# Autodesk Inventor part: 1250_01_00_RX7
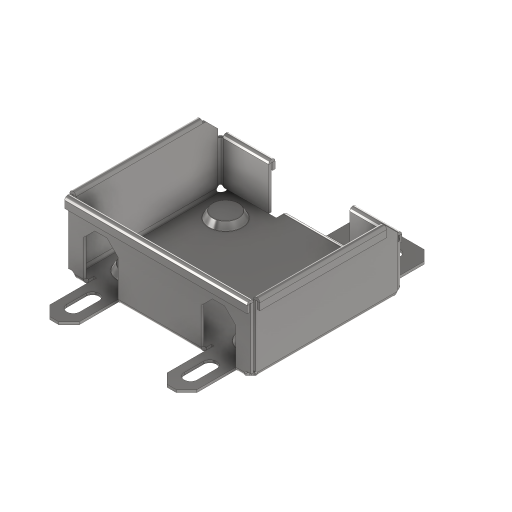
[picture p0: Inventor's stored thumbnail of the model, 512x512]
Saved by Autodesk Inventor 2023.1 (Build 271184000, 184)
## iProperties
Company: Fabian Stasiak CAD Consulting
Category: Autodesk® Inventor® Tutorial Series
RuleStatus: InUse
Created: 2005-11
Part Number: 1250_01_00_RX7
Material: Steel
Document SubType Name: Sheet Metal
Designer: F.Stasiak
Density: 7.85 g/cm^3
Sheet Metal Rule: Steel 2.5 mm/Round
Flat Pattern Width: 32.8562 cm
Flat Pattern Length: 33.224 cm
Flat Pattern Area: 1091.62 cm^2
Sheet Metal Width: 328,562 mm
Sheet Metal Length: 332,240 mm
Sheet Metal Area: 109161,518 mm^2
Appearance: Semi-Polished
Description: Mounting Box RX7
Catalog Web Link: www.expertbooks.eu
FLATAREA: =<FLAT PATTERN AREA>
Thickness: 2,5
Author: F.Stasiak
Subject: Sheet Metal Design. Basic and Advanced techniques
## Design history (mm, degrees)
node "Powierzchnia1"
  sketch "Szkic2"
    geometry: L1 (-75, 90)-(75, 90); L2 (75, 90)-(75, -90); L3 (75, -90)-(-75, -90); L4 (-75, -90)-(-75, 90); L5 (0, 90)-(0, -90); 2 further points
    constraints: 10 end point, 3 midpoint, 2 parallel, 1 coincident, 1 horizontal, 1 perpendicular
    dimensions: "d2" = 150 distance of L2.end L3.end; "d3" = 180 distance of L1.end L2.end
node "Kołnierz6"
feature "Fazowanie narożnika3" dims "d68" = 20, "d69" = 6, angle "d70" = 45 deg
node "Kołnierz7"
feature "Narożnik4" dims "d156" = 10 (= CornerReliefSize), "d157" = 2.5 (= BendRadius), "d158" = 2.5 (= GapSize), "d159" = 0, "d160" = 10, "d244" = 2.5 (derived)
feature "Narożnik5" dims "d161" = 10 (= CornerReliefSize), "d162" = 2.5 (= BendRadius), "d163" = 2.5 (= GapSize), "d164" = 0, "d165" = 10, "d244" = 2.5 (derived)
node "Płaszczyzna konstrukcyjna2"
node "Powierzchnia3"
  sketch "Szkic11"
    geometry: L1 (-231, 119.076)-(-195, 119.076); L2 (-195, 119.076)-(-195, 49.076); L3 (-195, 49.076)-(-231, 49.076); L4 (-231, 49.076)-(-231, 119.076); L5 (-142.5, 44.076)-(-145, 44.076) reference; L6 (-142.5, 124.076)-(-145, 124.076) reference; L7 (-145, 167.518)-(-145, 0.634) reference; 3 further points
    constraints: 8 end point, 2 parallel, 1 horizontal, 1 perpendicular
    dimensions: "d82" = 5 distance between parallel lines of L5 L3; "d83" = 5 distance between parallel lines of L6 L1 (= d82); "d84" = 36 distance of L1.start L1.end; "d85" = 50 distance between parallel lines of L7 L2
feature "Fazowanie narożnika4" dims "d91" = 10, "d92" = 6, angle "d93" = 45 deg
feature "Gięcie10" dims "d94" = 2.5 (= BendReliefWidth), "d95" = 1.25 (= BendReliefDepth), "d96" = 5 (= MinimumRemnant), "d97" = 2.5 (= BendRadius), "d98" = 2.5 (= BendRadius), "d244" = 2.5 (derived), "SeamGap" = 0.01
sketch "Szkic19"
  geometry: L1 (-145, 167.518)-(-145, 119.076) reference; L2 (-145, 49.076)-(-145, 0.634) reference; L3 (-151.893, 49.076)-(-145, 49.076) reference; L4 (-151.893, 119.076)-(-151.893, 49.076) reference; L5 (-145, 119.076)-(-151.893, 119.076) reference; L6 (-145, 167.518)-(-145, 119.076) reference; L7 (7.645, 174.076)-(71.087, 174.076) reference; L8 (71.087, 174.076)-(71.087, -5.924) reference; L9 (71.087, -5.924)-(7.645, -5.924) reference; L10 (6.087, 168.153)-(6.087, 0) reference; L11 (-0.924, 169.076)-(-139.076, 169.076) reference; L12 (0, 0)-(0, 168.153) reference; L13 (-139.076, -0.924)-(-0.924, -0.924) reference; L14 (3.043, 1.033)-(3.043, 167.12) reference; L15 (53, 159.076)-(-5, 159.076); L16 (-5, 159.076)-(-5, 125.076); L17 (-5, 125.076)-(53, 125.076); L18 (53, 125.076)-(53, 159.076); L19 (-139.076, 174.076)-(-0.924, 174.076) reference; A1 r 5 centre (-143.043, 172.12) between (-145, 167.518) and (-139.076, 169.076) reference; A2 r 5 centre (3.043, 172.12) between (-0.924, 169.076) and (7.645, 174.076) reference; A3 r 5 centre (3.043, -3.967) between (7.645, -5.924) and (-0.924, -0.924) reference; A4 r 5 centre (-143.043, -3.967) between (-139.076, -0.924) and (-145, 0.634) reference; 1 further point
  constraints: 8 end point, 2 parallel, 1 horizontal, 1 perpendicular
  dimensions: "d166" = 34 distance of L15.end L16.end; "d167" = 15 distance between parallel lines of L15 L19; "d168" = 58 distance of L16.end L17.end; "d169" = 140 distance between parallel lines of L1 L16
feature "Wytnij2" sketch "Szkic19" dims "d170" = 2.5 (= Thickness), "d171" = 0
node "Kołnierz9"
feature "Fazowanie narożnika7" dims "d182" = 10, "d183" = 6, angle "d184" = 45 deg
feature "Fazowanie narożnika8" dims "d185" = 11, "d186" = 6, angle "d187" = 45 deg
mirror "Lustro2"
feature "Zawinięcie obrzeża6" dims "d188" = 2.5 (= BendReliefWidth), "d189" = 1.25 (= BendReliefDepth), "d190" = 5 (= MinimumRemnant), "d191" = 2.5 (= BendRadius), "d192" = 10 (= 4 x Thickness), "d193" = 1.25 (= 0.5 x Thickness), "d194" = 0.625 (= 0.5 x d193), "d244" = 2.5 (derived), "SeamGap" = 0.01
feature "Zawinięcie obrzeża7" dims "d195" = 2.5 (= BendReliefWidth), "d196" = 1.25 (= BendReliefDepth), "d197" = 5 (= MinimumRemnant), "d198" = 2.5 (= BendRadius), "d199" = 10 (= 4 x Thickness), "d200" = 1.25 (= 0.5 x Thickness), "d201" = 0.625 (= 0.5 x d200), "d244" = 2.5 (derived), "SeamGap" = 0.01
feature "Zawinięcie obrzeża8" dims "d202" = 2.5 (= BendReliefWidth), "d203" = 1.25 (= BendReliefDepth), "d204" = 5 (= MinimumRemnant), "d205" = 2.5 (= BendRadius), "d206" = 10 (= 4 x Thickness), "d207" = 1.25 (= 0.5 x Thickness), "d208" = 0.625 (= 0.5 x d207), "d244" = 2.5 (derived), "SeamGap" = 0.01
feature "Zawinięcie obrzeża9" dims "d209" = 2.5 (= BendReliefWidth), "d210" = 1.25 (= BendReliefDepth), "d211" = 5 (= MinimumRemnant), "d212" = 2.5 (= BendRadius), "d213" = 10 (= 4 x Thickness), "d214" = 1.25 (= 0.5 x Thickness), "d215" = 0.625 (= 0.5 x d214), "d244" = 2.5 (derived), "SeamGap" = 0.01
feature "Zawinięcie obrzeża10" dims "d216" = 2.5 (= BendReliefWidth), "d217" = 1.25 (= BendReliefDepth), "d218" = 5 (= MinimumRemnant), "d219" = 2.5 (= BendRadius), "d220" = 10 (= 4 x Thickness), "d221" = 1.25 (= 0.5 x Thickness), "d222" = 0.625 (= 0.5 x d221), "d244" = 2.5 (derived), "SeamGap" = 0.01
sketch "Szkic26"
  geometry: L1 (190.076, 31.5)-(190.076, 22.5) reference; L2 (134.076, 157.5)-(134.076, 128.5); L3 (133.736, 41.5)-(134.076, 12.5); L4 (190.076, 27)-(133.906, 27); L5 (189.537, 143)-(134.076, 143); 3 further points
  constraints: 8 end point, 5 midpoint, 1 parallel
sketch "Szkic27"
  geometry: L1 (-195, 119.076)-(-195, 49.076) reference; L2 (-231, 59.076)-(-231, 109.076) reference; L3 (-195, 84.076)-(-231, 84.076); 2 further points
  constraints: 3 midpoint, 2 end point
sketch "Szkic28"
  geometry: L1 (0, 0)-(138.153, 0) reference; L2 (144.076, 50)-(144.076, 1.558) reference; L3 (138.153, 170)-(0, 170) reference; L4 (-0.924, 126)-(-0.924, 44) reference; L5 (29.076, 25)-(119.076, 25); L6 (119.076, 25)-(119.076, 145); L7 (119.076, 145)-(29.076, 145); L8 (29.076, 145)-(29.076, 25); 1 further point
  constraints: 8 end point, 2 parallel, 1 horizontal, 1 perpendicular
  dimensions: "d229" = 25 distance between parallel lines of L5 L1; "d230" = 25 distance between parallel lines of L3 L7 (= d229); "d231" = 25 distance between parallel lines of L2 L6; "d232" = 30 distance between parallel lines of L4 L8
feature "iFeature18:1"
feature "iFeature18:2"
feature "iFeature5:1"
node "Definicja strony A"
feature "ع耀ظ耀ص耀ش耀س耀خ耀ح耀ا耀" dims "d0" = 180 deg, "d2" = 150, "d3" = 180, "d4" = 2.5 (= BendRadius), "d56" = 2.5 (= BendReliefWidth), "d57" = 1.25 (= BendReliefDepth), "d58" = 5 (= MinimumRemnant), "d59" = 2.5 (= BendRadius), "d60" = 70 (= WW), "d61" = 90 deg, "d62" = 2.5 (= BendRadius), "d63" = 10 (= CornerReliefSize), "d64" = 2.5 (= GapSize), "d65" = 2.5 (= JacobiRadiusSize), "d66" = 10, "d67" = 10, "d68" = 20, "d69" = 6, "d70" = 45 deg, "d71" = 2.5 (= BendReliefWidth), "d72" = 1.25 (= BendReliefDepth), "d73" = 5 (= MinimumRemnant), "d74" = 2.5 (= BendRadius), "d75" = 50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
feature "ٱ耀ٰ耀٭耀٬耀٫耀٦耀٥耀ٟ耀" dims "d0" = 180 deg, "d2" = 150, "d3" = 180, "d4" = 2.5 (= BendRadius), "d56" = 2.5 (= BendReliefWidth), "d57" = 1.25 (= BendReliefDepth), "d58" = 5 (= MinimumRemnant), "d59" = 2.5 (= BendRadius), "d60" = 70 (= WW), "d61" = 90 deg, "d62" = 2.5 (= BendRadius), "d63" = 10 (= CornerReliefSize), "d64" = 2.5 (= GapSize), "d65" = 2.5 (= JacobiRadiusSize), "d66" = 10, "d67" = 10, "d68" = 20, "d69" = 6, "d70" = 45 deg, "d71" = 2.5 (= BendReliefWidth), "d72" = 1.25 (= BendReliefDepth), "d73" = 5 (= MinimumRemnant), "d74" = 2.5 (= BendRadius), "d75" = 50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
node "Bryła1"
node "Korpusy bryłowe"
node "Korpusy powierzchniowe"
feature "Płyta1" dims "d244" = 2.5 (derived)
sketch "Szkic9"
  geometry: L1 (0, 70)-(-150, 70); L2 (-150, 70)-(-150, 0); 1 other entity
  constraints: 4 end point, 4 other
feature "Płyta8" dims "d56" = 2.5 (= BendReliefWidth), "d57" = 1.25 (= BendReliefDepth), "d58" = 5 (= MinimumRemnant), "d59" = 2.5 (= BendRadius), "d60" = 70 (= WW), "d61" = 90 deg, "d62" = 2.5 (= BendRadius), "d63" = 10 (= CornerReliefSize), "d64" = 2.5 (= GapSize), "d65" = 2.5 (= JacobiRadiusSize), "d66" = 10, "d67" = 10, "d244" = 2.5 (derived), "SeamGap" = 0.01
feature "Gięcie7" dims "d56" = 2.5 (= BendReliefWidth), "d57" = 1.25 (= BendReliefDepth), "d58" = 5 (= MinimumRemnant), "d59" = 2.5 (= BendRadius), "d60" = 70 (= WW), "d61" = 90 deg, "d62" = 2.5 (= BendRadius), "d244" = 2.5 (derived), "SeamGap" = 0.01
feature "Narożnik1" dims "d60" = 70 (= WW), "d61" = 90 deg, "d63" = 10 (= CornerReliefSize), "d64" = 2.5 (= GapSize), "d65" = 2.5 (= JacobiRadiusSize)
sketch "Szkic10"
  geometry: L1 (50, 0)-(50, 45); L2 (50, 45)-(0, 45); 1 other entity
  constraints: 4 end point, 4 other
feature "Płyta9" dims "d71" = 2.5 (= BendReliefWidth), "d72" = 1.25 (= BendReliefDepth), "d73" = 5 (= MinimumRemnant), "d74" = 2.5 (= BendRadius), "d75" = 50, "d76" = 90 deg, "d77" = 2.5 (= BendRadius), "d78" = 10 (= CornerReliefSize), "d79" = 2.5 (= GapSize), "d80" = 2.5 (= JacobiRadiusSize), "d244" = 2.5 (derived), "SeamGap" = 0.01
feature "Gięcie8" dims "d71" = 2.5 (= BendReliefWidth), "d72" = 1.25 (= BendReliefDepth), "d73" = 5 (= MinimumRemnant), "d74" = 2.5 (= BendRadius), "d75" = 50, "d76" = 90 deg, "d77" = 2.5 (= BendRadius), "d244" = 2.5 (derived), "SeamGap" = 0.01
feature "Narożnik2" dims "d75" = 50, "d76" = 90 deg, "d78" = 10 (= CornerReliefSize), "d79" = 2.5 (= GapSize), "d80" = 2.5 (= JacobiRadiusSize)
feature "Płyta10" dims "d86" = 2.5 (= BendRadius), "d87" = 2.5 (= BendReliefWidth), "d89" = 5 (= MinimumRemnant), "d244" = 2.5 (derived)
feature "Gięcie9" dims "d86" = 2.5 (= BendRadius), "d87" = 2.5 (= BendReliefWidth), "d88" = 1.25 (= BendReliefDepth), "d89" = 5 (= MinimumRemnant), "d90" = 2.5 (= BendRadius), "d244" = 2.5 (derived), "SeamGap" = 0.01
sketch "Szkic20"
  geometry: L1 (0, -31.5)-(0, -2.5); L2 (0, -2.5)-(-56, -2.5); L3 (-56, -2.5)-(-56, -31.5); L4 (-56, -31.5)-(0, -31.5)
  constraints: 8 end point
feature "Płyta12" dims "d172" = 2.5 (= BendReliefWidth), "d173" = 1.25 (= BendReliefDepth), "d174" = 5 (= MinimumRemnant), "d175" = 2.5 (= BendRadius), "d176" = 56, "d177" = 0, "d178" = 2.5 (= BendRadius), "d179" = 10 (= CornerReliefSize), "d180" = 2.5 (= GapSize), "d181" = 2.5 (= JacobiRadiusSize), "d244" = 2.5 (derived), "SeamGap" = 0.01
feature "Gięcie12" dims "d172" = 2.5 (= BendReliefWidth), "d173" = 1.25 (= BendReliefDepth), "d174" = 5 (= MinimumRemnant), "d175" = 2.5 (= BendRadius), "d176" = 56, "d177" = 0, "d178" = 2.5 (= BendRadius), "d244" = 2.5 (derived), "SeamGap" = 0.01
feature "Narożnik6" dims "d176" = 56, "d177" = 0, "d179" = 10 (= CornerReliefSize), "d180" = 2.5 (= GapSize), "d181" = 2.5 (= JacobiRadiusSize)
sketch "Szkic21"
  geometry: L1 (2.5, 0)-(0, 0); L2 (-1.25, 0)-(-1.25, -6.875); L3 (-1.25, -6.875)-(-3.75, -6.875); L4 (-3.75, -6.875)-(-3.75, 0); A1 r 0.625 centre (-0.625, 0) between (0, 0) and (-1.25, 0); A2 r 3.125 centre (-0.625, 0) between (2.5, 0) and (-3.75, 0)
  constraints: 8 end point, 4 point on circle
sketch "Szkic22"
  geometry: L1 (2.5, 0)-(0, 0); L2 (-1.25, 0)-(-1.25, -6.875); L3 (-1.25, -6.875)-(-3.75, -6.875); L4 (-3.75, -6.875)-(-3.75, 0); A1 r 0.625 centre (-0.625, 0) between (0, 0) and (-1.25, 0); A2 r 3.125 centre (-0.625, 0) between (2.5, 0) and (-3.75, 0)
  constraints: 8 end point, 4 point on circle
sketch "Szkic23"
  geometry: L1 (2.5, 0)-(0, 0); L2 (-1.25, 0)-(-1.25, -6.875); L3 (-1.25, -6.875)-(-3.75, -6.875); L4 (-3.75, -6.875)-(-3.75, 0); A1 r 0.625 centre (-0.625, 0) between (0, 0) and (-1.25, 0); A2 r 3.125 centre (-0.625, 0) between (2.5, 0) and (-3.75, 0)
  constraints: 8 end point, 4 point on circle
sketch "Szkic24"
  geometry: L1 (2.5, 0)-(0, 0); L2 (-1.25, 0)-(-1.25, -6.875); L3 (-1.25, -6.875)-(-3.75, -6.875); L4 (-3.75, -6.875)-(-3.75, 0); A1 r 0.625 centre (-0.625, 0) between (0, 0) and (-1.25, 0); A2 r 3.125 centre (-0.625, 0) between (2.5, 0) and (-3.75, 0)
  constraints: 8 end point, 4 point on circle
sketch "Szkic25"
  geometry: L1 (2.5, 0)-(0, 0); L2 (-1.25, 0)-(-1.25, -6.875); L3 (-1.25, -6.875)-(-3.75, -6.875); L4 (-3.75, -6.875)-(-3.75, 0); A1 r 0.625 centre (-0.625, 0) between (0, 0) and (-1.25, 0); A2 r 3.125 centre (-0.625, 0) between (2.5, 0) and (-3.75, 0)
  constraints: 8 end point, 4 point on circle
feature "Definicja1"
